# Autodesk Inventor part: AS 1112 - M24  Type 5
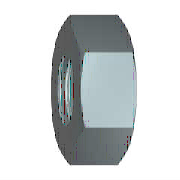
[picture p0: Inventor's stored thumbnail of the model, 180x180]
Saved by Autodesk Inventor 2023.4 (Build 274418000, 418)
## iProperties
Created: 2022-02
Part Number: AS 1112 - M24  Type 5
Material: Acier, doux
Description: Ecrous hexagonaux métriques ISO, comprenant des écrous bas, à créneaux et à créneaux dégagés
Document SubType Name: Modeling
Standard: AS 1112
Designer: bruno
Standards Organization: AS
Language: fr-FR
Size Designation: M24  Type 5
Categories: <MemberInstance><Categories><Category DisplayName="Visserie" InternalName="e4da775c-781d-43d5-af7c-5136215cf5a6" Mnemonic="FSTN"><Category DisplayName="Ecrous"
Density: 7.85 g/cm^3
Appearance: Semi-poli
IsCustomPart: 0
Author: bruno
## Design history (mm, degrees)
workaxis "Work Axis1"
workplane "Work Plane1"
sketch "Esquisse1"
  geometry: L1 (-20.785, 0)-(-10.392, 18); L2 (-10.392, 18)-(10.392, 18); L3 (10.392, 18)-(20.785, 0); L4 (20.785, 0)-(10.392, -18); L5 (10.392, -18)-(-10.392, -18); L6 (-10.392, -18)-(-20.785, 0); 2 further points
  constraints: 12 end point, 1 coincident, 1 horizontal, 11 other
  dimensions: "d0" = 41.56922 distance of L3.end L1.start (= 1.1547 x SW)
extrude "Corps" new body sketch "Esquisse1" distance "d1" = 21.5 (= KOH); taper "d2" = 0 deg
revolve "Chanfrein1" stored, may be unused: angle "d7" = 90 deg
sketch "Esquisse3"
  geometry: A1 r 18 centre (0, 0) between (-9, -15.588) and (9, -15.588) reference; 1 further point
  constraints: 1 coincident
hole "Filetage" sketch "Esquisse3" diameter "d25" = 20.752; stored, may be unused: countersink angle "d29" = 82 deg, drill point angle "d31" = 118 deg; dims "d26" = 6, "d27" = 4, "d28" = 2, "d30" = 8
body "Solid1"
chamfer "Chanfrein2" distance "d8" = 1.6238 (= -0.5 x GD1 + 0.5 x NND); stored, may be unused: angle "d9" = 30 deg, second distance "d40" = 1.6238 (= -0.5 x GD1 + 0.5 x NND)
chamfer "Chanfrein3" distance "d10" = 1.6238 (= -0.5 x GD1 + 0.5 x NND); stored, may be unused: angle "d11" = 30 deg, second distance "d41" = 1.6238 (= -0.5 x GD1 + 0.5 x NND)
sketch "Esquisse2"
  geometry: L1 (0, 10.392)-(0, 20.785) reference; L2 (0, 20.785)-(21.5, 20.785) reference; L3 (21.5, 10.392)-(21.5, 20.785) reference; L4 (-4.3, 0)-(25.8, 0) reference; L5 (1.608, 20.785)-(0, 18); L6 (19.892, 20.785)-(21.5, 18)
  constraints: 4 end point, 4 point on line
  dimensions: "d3" = 30 deg angle of L1 L5 (= ANG1); "d4" = 30 deg angle of L3 L6 (= ANG2); "d5" = 36 diameter of L5.end L4 (= SW0); "d6" = 36 diameter of L6.end L4 (= SW01)
other parameters: "ANG1" = 30 deg [user parameter; used in 1 equation term], "ANG2" = 30 deg [user parameter; used in 1 equation term], "NND" = 24 [user parameter; used in 4 equation terms], "KOH" = 21.5 [user parameter; used in 1 equation term], "SW" = 36 [user parameter; used in 4 equation terms], "SW0" = 36 (= SW) [user parameter; used in 1 equation term], "SW01" = 36 (= SW) [user parameter; used in 1 equation term], "GD1" = 20.7524 (computed from THREADDIA, PTC, TOA) [user parameter; used in 4 equation terms], "d13" = 0, "d14" = 0, "d39" = 0, "d42" = 0, "GUL" = 1.6238 (= 0.541266 x PTC) [user parameter], "TPU" = 3.33333 (computed from PTC) [user parameter], "WFT" = 0.8 [user parameter], "THREADDIA" = 24 [user parameter; used in 1 equation term], "TOA" = 30 deg [user parameter; used in 1 equation term], "PTC" = 3 [user parameter; used in 4 equation terms], "E0" = 41.58 (= 1.155 x SW) [user parameter], "GAL" = 1.6238 (= 0.541266 x PTC) [user parameter]
